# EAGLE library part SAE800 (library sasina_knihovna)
Gong se 3, 2 nebo 1 tonem.
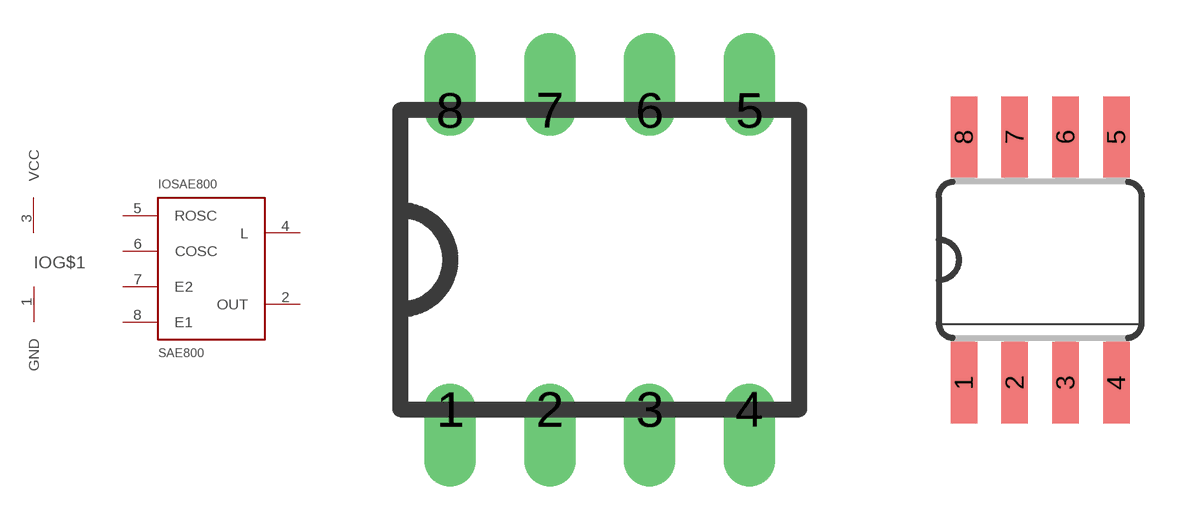
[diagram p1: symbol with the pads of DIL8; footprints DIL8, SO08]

Designator prefix IO; gates G$1=NAPAJENI SAE800=SAE800

## SAE800N  [DIL8]
1  G$1:GND  pwr
2  SAE800:OUT  out
3  G$1:VCC  pwr
4  SAE800:L  in
5  SAE800:ROSC  pas
6  SAE800:COSC  pas
7  SAE800:E2  in
8  SAE800:E1  in

## SAE800D  [SO08]
Pads as for DIL8

## Footprint DIL8 (pad centres in mm)
drill 0.8 offset: 1 0,-1.27; 2 2.54,-1.27; 3 5.08,-1.27; 4 7.62,-1.27; 5 7.62,6.35; 6 5.08,6.35; 7 2.54,6.35; 8 0,6.35

## Footprint SO08 (pad centres in mm)
Small Outline package 150 mil
smd 0.66 x 2.032: 1 -1.905,-3.073; 2 -0.635,-3.073; 3 0.635,-3.073; 4 1.905,-3.073; 5 1.905,3.073; 6 0.635,3.073; 7 -0.635,3.073; 8 -1.905,3.073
